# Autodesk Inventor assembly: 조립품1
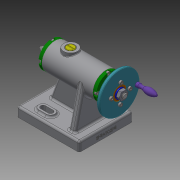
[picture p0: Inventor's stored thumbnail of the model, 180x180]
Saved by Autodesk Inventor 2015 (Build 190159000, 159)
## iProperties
Created: 2022-06
Part Number: 조립품1
Document SubType Name: Assembly
Designer: 10462
Author: 10462
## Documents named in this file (18)
- C:\Users\10462\Desktop\720606V1010\조립품1.iam
- C:\Users\10462\Desktop\720606V1010\Ű 4 x 4 x 10.ipt
- C:\Users\10462\Desktop\720606V1010\나사.ipt
- C:\Users\10462\Desktop\720606V1010\나사축.ipt
- C:\Users\10462\Desktop\720606V1010\너트 M8.ipt
- C:\Users\10462\Desktop\720606V1010\돌림판.ipt
- C:\Users\10462\Desktop\720606V1010\멈춤나사 M3.ipt
- C:\Users\10462\Desktop\720606V1010\볼트 M3.ipt
- C:\Users\10462\Desktop\720606V1010\부시.ipt
- C:\Users\10462\Desktop\720606V1010\부품1.ipt
- C:\Users\10462\Desktop\720606V1010\센터.ipt
- C:\Users\10462\Desktop\720606V1010\센터홀더.ipt
- C:\Users\10462\Desktop\720606V1010\슬리브.ipt
- C:\Users\10462\Desktop\720606V1010\와셔.ipt
- C:\Users\10462\Desktop\720606V1010\중공축.ipt
- C:\Users\10462\Desktop\720606V1010\커버.ipt
- C:\Users\10462\Desktop\720606V1010\플랜지.ipt
- C:\Users\10462\Desktop\720606V1010\핸들.ipt
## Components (3 placed, 3 different names)
1. Ű 4 x 4 x 10:1
2. 플랜지:1
3. 핸들:1 — 플러쉬:4
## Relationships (1: Flush 1)
- 플러쉬:4 [Flush]: 핸들:1
